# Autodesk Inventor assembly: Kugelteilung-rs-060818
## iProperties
Manager: Dr.-Ing. Roland Schröder
Company: www.Das-Entwicklungsbuero.de
Created: 2006-08
Part Number: Kugelteilung-rs-060818
Project: 11307
Document SubType Name: Assembly
Designer: rsc
Engineer: Dr.-Ing. Roland Schröder
Author: rsc
Oberflächen: Ra 3,2
Toleranzen: ISO 2768 - m
a: 17.000 oE
b: 10.000 mm
d: 34.000 mm
